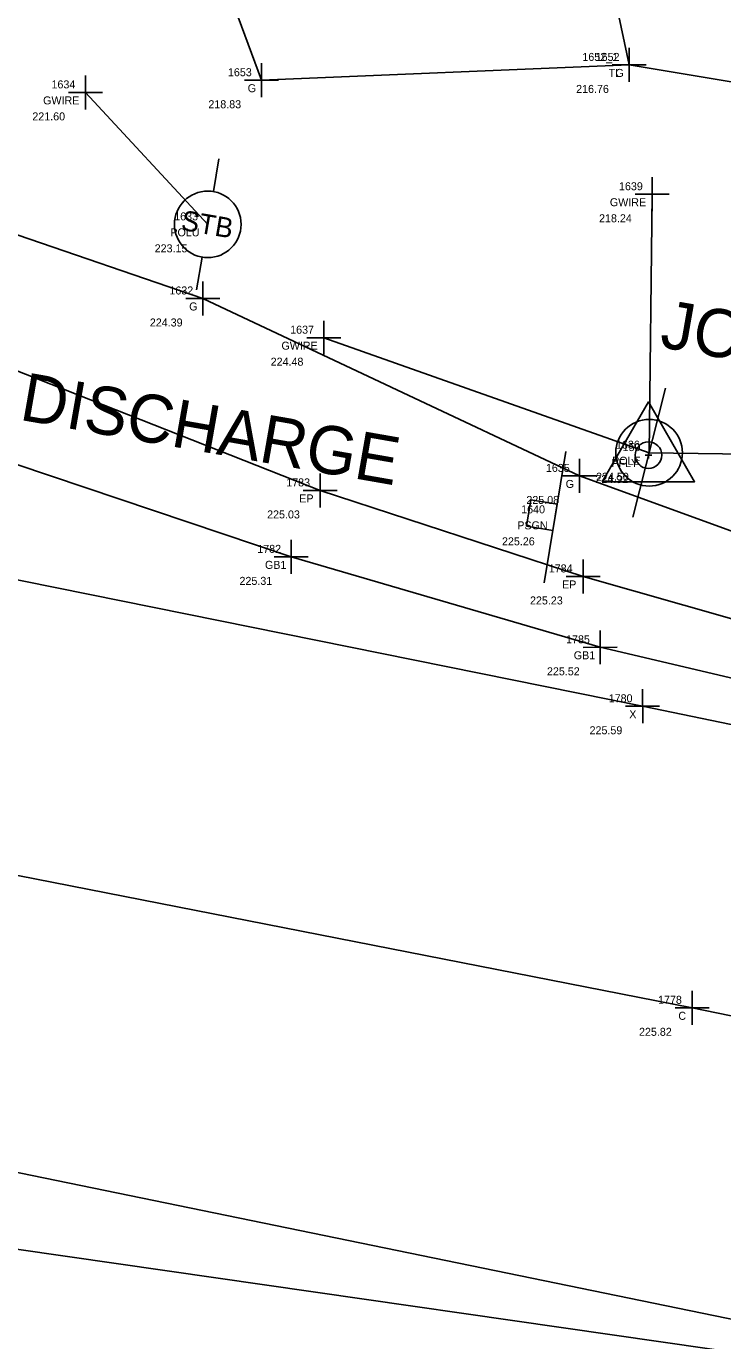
# Model space of a CAD drawing. Extents: x 1158983 to 1160032, y 610902 to 611573.
# Drawn here: x 1159291.24 to 1159317.32, y 611268.4 to 611317.69 of the extents above; entities that cross this region are included whole.
import ezdxf

# ---------------------------------------------------------------- set-up
doc = ezdxf.new("R2010")
doc.units = 0
for name, color, linetype in [('Default', 7, 'Continuous'), ('S_Control_Temp_Traverse', 7, 'Continuous'), ('S_Field_Code', 7, 'Continuous'), ('S_Ground_Elevation', 7, 'Continuous'), ('S_Guardrail_Beam', 7, 'Continuous'), ('S_Point_Elevation', 7, 'Continuous'), ('S_Point_Name', 7, 'Continuous'), ('S_Roadway_Centerline', 7, 'Continuous'), ('S_Roadway_Edge_Pavement', 7, 'Continuous'), ('S_Roadway_Edge_TW', 7, 'Continuous'), ('S_Survey_Shot', 7, 'Continuous'), ('S_Text', 7, 'Continuous'), ('S_Traffic_Sign_SinglePost', 7, 'Continuous'), ('S_Trees_TreeLine', 7, 'Continuous'), ('S_Utilities_GuyWire3', 7, 'Continuous'), ('S_Utilities_Pole_Power', 7, 'Continuous'), ('S_Utilities_Pole_Stub', 7, 'Continuous')]:
    doc.layers.add(name, color=color, linetype=linetype)

msp = doc.modelspace()

# ---------------------------------------------------------------- linework, layer by layer
at = {"layer": 'Default'}
for p, q in [((1159298.033, 611310.26), (1159298.033, 611310.26)), ((1159314.567, 611301.697), (1159314.567, 611301.697)), ((1159311.043, 611299.275), (1159311.043, 611299.275))]:
    msp.add_line(p, q, dxfattribs=at)
at = {"layer": 'S_Control_Temp_Traverse'}
for p, q in [((1159314.416, 611301.609), (1159314.666, 611301.609)), ((1159314.541, 611301.734), (1159314.541, 611301.484))]:
    msp.add_line(p, q, dxfattribs=at)
msp.add_lwpolyline([(1159312.812, 611300.611), (1159316.27, 611300.611), (1159314.541, 611303.605)], close=True, dxfattribs=at)
msp.add_circle((1159314.541, 611301.609), 0.499, dxfattribs=at)
at = {"layer": 'S_Ground_Elevation'}
for points in [[(1159352.149, 611311.344), (1159339.531, 611314.728), (1159324.665, 611314.427), (1159313.821, 611316.237), (1159300.045, 611315.663), (1159295.131, 611328.971), (1159291.342, 611351.557), (1159307.492, 611346.1), (1159310.1, 611324.165)], [(1159281.814, 611347.99), (1159279.491, 611333.481), (1159281.536, 611323.046), (1159282.88, 611313.648), (1159290.494, 611310.007), (1159297.852, 611307.481), (1159311.956, 611300.827), (1159323.804, 611296.524), (1159327.594, 611297.338), (1159333.265, 611297.96)]]:
    msp.add_lwpolyline(points, dxfattribs=at)
at = {"layer": 'S_Guardrail_Beam'}
for points in [[(1159275.939, 611307.136), (1159288.272, 611302.132), (1159301.161, 611297.793), (1159312.728, 611294.402), (1159333.178, 611289.596)], [(1159331.21, 611265.209), (1159318.741, 611267.819), (1159270.451, 611274.775), (1159214.189, 611285.337), (1159152.222, 611298.369), (1159139.375, 611300.216), (1159124.684, 611301.028)]]:
    msp.add_lwpolyline(points, dxfattribs=at)
at = {"layer": 'S_Roadway_Centerline'}
msp.add_lwpolyline([(1159006.602, 611348.691), (1159057.735, 611336.354), (1159096.909, 611327.465), (1159130.176, 611319.741), (1159165.906, 611311.781), (1159220.187, 611300.272), (1159273.601, 611289.244), (1159316.176, 611280.885), (1159332.053, 611277.617)], dxfattribs=at)
at = {"layer": 'S_Roadway_Edge_Pavement'}
msp.add_lwpolyline([(1159010.626, 611363.406), (1159061.319, 611351.387), (1159100.337, 611342.028), (1159133.857, 611334.48), (1159169.141, 611326.651), (1159225.717, 611315.753), (1159228.967, 611317.398), (1159231.047, 611319.517), (1159252.68, 611317.317), (1159261.737, 611314.051), (1159263.333, 611313.256), (1159275.665, 611310.381), (1159289.771, 611305.203), (1159302.246, 611300.284), (1159312.093, 611297.059), (1159323.315, 611293.855), (1159323.064, 611292.34), (1159324.775, 611291.223), (1159333.176, 611289.409)], dxfattribs=at)
at = {"layer": 'S_Roadway_Edge_TW'}
for points in [[(1159009.832, 611359.245), (1159060.49, 611346.863), (1159099.079, 611338.191), (1159133.188, 611330.52), (1159167.952, 611322.679), (1159223.507, 611310.762), (1159275.252, 611300.093), (1159314.324, 611292.191), (1159332.908, 611288.341)], [(1159003.943, 611338.028), (1159051.315, 611326.497), (1159095.593, 611316.459), (1159127.862, 611309.062), (1159159.052, 611302.124), (1159217.512, 611289.831), (1159271.817, 611278.631), (1159319.29, 611268.871), (1159331.181, 611266.673)]]:
    msp.add_lwpolyline(points, dxfattribs=at)
at = {"layer": 'S_Survey_Shot'}
for p, q in [((1159313.823, 611315.601), (1159313.82, 611316.874)), ((1159313.823, 611315.601), (1159313.82, 611316.874)), ((1159293.451, 611314.571), (1159293.449, 611315.843)), ((1159300.047, 611315.027), (1159300.044, 611316.299)), ((1159313.185, 611316.236), (1159314.457, 611316.239)), ((1159313.185, 611316.236), (1159314.457, 611316.239)), ((1159313.821, 611316.237), (1159313.821, 611316.237)), ((1159313.821, 611316.237), (1159313.821, 611316.237)), ((1159299.409, 611315.662), (1159300.682, 611315.664)), ((1159300.045, 611315.663), (1159300.045, 611315.663)), ((1159292.814, 611315.206), (1159294.086, 611315.209)), ((1159293.45, 611315.207), (1159293.45, 611315.207)), ((1159314.682, 611310.752), (1159314.679, 611312.024)), ((1159314.044, 611311.387), (1159315.317, 611311.389)), ((1159314.68, 611311.388), (1159314.68, 611311.388)), ((1159297.854, 611306.844), (1159297.851, 611308.117)), ((1159297.216, 611307.479), (1159298.489, 611307.482)), ((1159297.852, 611307.481), (1159297.852, 611307.481)), ((1159302.38, 611305.374), (1159302.377, 611306.646)), ((1159301.742, 611306.009), (1159303.015, 611306.011)), ((1159302.378, 611306.01), (1159302.378, 611306.01)), ((1159311.957, 611300.191), (1159311.955, 611301.463)), ((1159302.248, 611299.648), (1159302.245, 611300.92)), ((1159311.32, 611300.826), (1159312.592, 611300.828)), ((1159311.956, 611300.827), (1159311.956, 611300.827)), ((1159301.61, 611300.283), (1159302.882, 611300.286)), ((1159302.246, 611300.284), (1159302.246, 611300.284)), ((1159301.163, 611297.157), (1159301.16, 611298.429)), ((1159300.525, 611297.792), (1159301.798, 611297.794)), ((1159301.161, 611297.793), (1159301.161, 611297.793)), ((1159312.095, 611296.423), (1159312.092, 611297.696)), ((1159311.457, 611297.058), (1159312.73, 611297.061)), ((1159312.093, 611297.059), (1159312.093, 611297.059)), ((1159312.729, 611293.766), (1159312.727, 611295.038)), ((1159312.092, 611294.4), (1159313.364, 611294.403)), ((1159312.728, 611294.402), (1159312.728, 611294.402)), ((1159314.325, 611291.555), (1159314.322, 611292.828)), ((1159313.687, 611292.19), (1159314.96, 611292.193)), ((1159314.324, 611292.191), (1159314.324, 611292.191)), ((1159316.178, 611280.249), (1159316.175, 611281.522)), ((1159315.54, 611280.884), (1159316.812, 611280.887)), ((1159316.176, 611280.885), (1159316.176, 611280.885))]:
    msp.add_line(p, q, dxfattribs=at)
at = {"layer": 'S_Traffic_Sign_SinglePost'}
msp.add_line((1159311.45, 611301.737), (1159310.636, 611296.813), dxfattribs=at)
msp.add_lwpolyline([(1159311.124, 611299.767), (1159310.961, 611298.783), (1159309.977, 611298.946), (1159310.139, 611299.93)], close=True, dxfattribs=at)
at = {"layer": 'S_Trees_TreeLine'}
msp.add_lwpolyline([(1159313.821, 611316.237), (1159307.492, 611346.1)], dxfattribs=at)
at = {"layer": 'S_Utilities_GuyWire3'}
for p, q in [((1159293.45, 611315.207), (1159293.45, 611315.207)), ((1159314.68, 611311.388), (1159314.68, 611311.388)), ((1159302.378, 611306.01), (1159302.378, 611306.01))]:
    msp.add_line(p, q, dxfattribs=at)
for points in [[(1159293.45, 611315.207), (1159298.033, 611310.26)], [(1159314.68, 611311.388), (1159314.567, 611301.697)], [(1159302.378, 611306.01), (1159314.567, 611301.697)], [(1159330.151, 611301.48), (1159314.567, 611301.697)]]:
    msp.add_lwpolyline(points, dxfattribs=at)
at = {"layer": 'S_Utilities_Pole_Power'}
msp.add_line((1159315.184, 611304.115), (1159313.95, 611299.28), dxfattribs=at)
msp.add_circle((1159314.567, 611301.697), 1.248, dxfattribs=at)
at = {"layer": 'S_Utilities_Pole_Stub'}
for p, q in [((1159298.454, 611312.72), (1159298.243, 611311.49)), ((1159297.822, 611309.031), (1159297.612, 611307.801))]:
    msp.add_line(p, q, dxfattribs=at)
msp.add_circle((1159298.033, 611310.26), 1.248, dxfattribs=at)

# ---------------------------------------------------------------- texts
at = {"layer": 'S_Field_Code'}
for s, p in [('TL', (1159313.049, 611315.787)), ('G', (1159313.306, 611315.787)), ('G', (1159299.53, 611315.213)), ('GWIRE', (1159291.865, 611314.757)), ('GWIRE', (1159313.096, 611310.938)), ('POLU', (1159296.632, 611309.81)), ('G', (1159297.337, 611307.031)), ('GWIRE', (1159300.794, 611305.56)), ('POLE', (1159313.18, 611301.247)), ('PFLY', (1159313.155, 611301.159)), ('G', (1159311.441, 611300.377)), ('EP', (1159301.46, 611299.834)), ('PSGN', (1159309.628, 611298.825)), ('GB1', (1159300.176, 611297.343)), ('EP', (1159311.307, 611296.609)), ('GB1', (1159311.743, 611293.952)), ('X', (1159313.823, 611291.741)), ('C', (1159315.661, 611280.435))]:
    msp.add_text(s, height=0.3, dxfattribs=at).set_placement(p)
at = {"layer": 'S_Point_Elevation'}
for s, p in [('216.76', (1159311.832, 611315.187)), ('216.76', (1159311.832, 611315.187)), ('218.83', (1159298.056, 611314.613)), ('221.60', (1159291.461, 611314.157)), ('218.24', (1159312.691, 611310.338)), ('223.15', (1159296.044, 611309.21)), ('224.39', (1159295.863, 611306.431)), ('224.48', (1159300.389, 611304.96)), ('224.92', (1159312.552, 611300.559)), ('224.50', (1159312.578, 611300.647)), ('225.08', (1159309.967, 611299.777)), ('225.03', (1159300.257, 611299.234)), ('225.26', (1159309.054, 611298.225)), ('225.31', (1159299.222, 611296.743)), ('225.23', (1159310.104, 611296.009)), ('225.52', (1159310.739, 611293.352)), ('225.59', (1159312.335, 611291.141)), ('225.82', (1159314.187, 611279.835))]:
    msp.add_text(s, height=0.3, dxfattribs=at).set_placement(p)
at = {"layer": 'S_Point_Name'}
for s, p in [('1652_1', (1159312.066, 611316.387)), ('1652', (1159312.565, 611316.387)), ('1653', (1159298.789, 611315.813)), ('1634', (1159292.179, 611315.357)), ('1639', (1159313.438, 611311.538)), ('1633', (1159296.776, 611310.41)), ('1632', (1159296.596, 611307.631)), ('1637', (1159301.12, 611306.16)), ('1636', (1159313.324, 611301.847)), ('150', (1159313.573, 611301.759)), ('1635', (1159310.7, 611300.977)), ('1783', (1159300.973, 611300.434)), ('1640', (1159309.774, 611299.425)), ('1782', (1159299.888, 611297.943)), ('1784', (1159310.806, 611297.209)), ('1785', (1159311.455, 611294.552)), ('1780', (1159313.053, 611292.341)), ('1778', (1159314.901, 611281.035))]:
    msp.add_text(s, height=0.3, dxfattribs=at).set_placement(p)
at = {"layer": 'S_Text'}
for s, rotation, p in [('NO FIREARMS DISCHARGE', 350.0683, (1159273.814, 611305.937)), ('JOINT 32 / 511 / 39', 350.044, (1159314.924, 611305.666))]:
    msp.add_text(s, height=1.8, rotation=rotation, dxfattribs=at).set_placement(p)
at = {"layer": 'S_Utilities_Pole_Stub'}
msp.add_text('STB', height=0.7485, rotation=350.2815, dxfattribs=at).set_placement((1159296.999, 611310.058))

doc.saveas('drawing.dxf')
